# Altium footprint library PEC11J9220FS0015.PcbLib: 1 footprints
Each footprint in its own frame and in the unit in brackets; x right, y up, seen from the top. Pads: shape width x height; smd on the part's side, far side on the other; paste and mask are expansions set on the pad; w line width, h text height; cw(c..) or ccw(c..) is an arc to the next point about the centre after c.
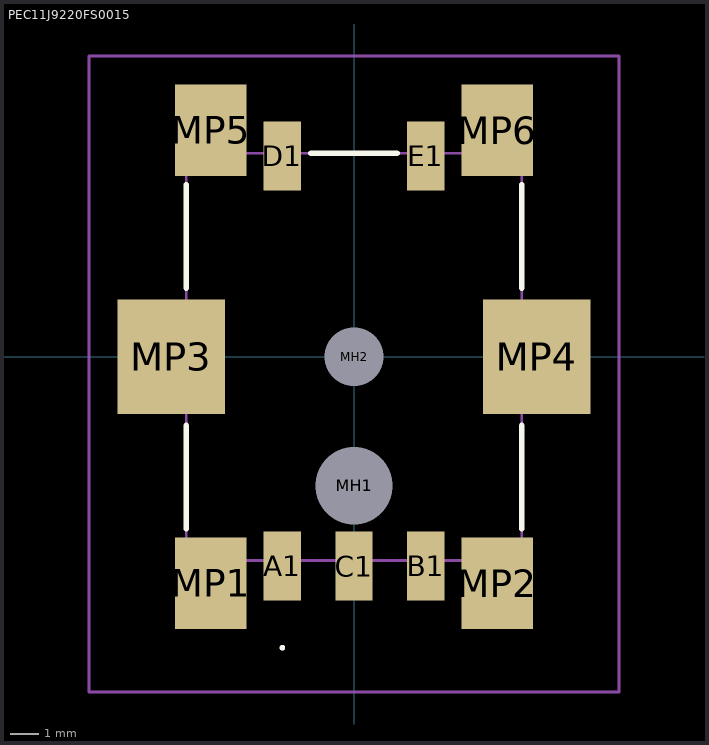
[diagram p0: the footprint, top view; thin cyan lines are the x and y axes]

## PEC11J9220FS0015 [mm]
pads (13):
  rect 1.3x2.4 smd: A1(-2.5,-7.3) B1(2.5,-7.3) C1(0,-7.3) D1(-2.5,7) E1(2.5,7)
  round 1.345 hole 2.69 unplated: MH1(0,-4.5)
  round 1.025 hole 2.05 unplated: MH2(0,0)
  rect 2.5x3.2 smd: MP1(-5,-7.9) MP2(5,-7.9) MP5(-5,7.9) MP6(5,7.9)
  rect 3.75x4 smd: MP3(-6.375,0) MP4(6.375,0)
Top Overlay:
  lines w0.1: -2.5,-10.2 -2.5,-10.2 ; -2.5,-10.2 ccw(c-2.5,-10.15) -2.5,-10.1 ; -2.5,-10.2 cw(c-2.5,-10.15) -2.5,-10.1 ; -2.5,-10.1 -2.5,-10.1
  lines w0.2: -5.85,-6 -5.85,-2.4 ; -5.85,2.4 -5.85,6 ; -1.5,7.1 1.5,7.1 ; 5.85,-6 5.85,-2.4 ; 5.85,2.4 5.85,6
Mechanical 15:
  lines w0.1: -5.85,-7.1 5.85,-7.1 5.85,7.1 -5.85,7.1 -5.85,-7.1
Mechanical 20:
  lines w0.1: -9.25,-11.7 9.25,-11.7 9.25,10.5 -9.25,10.5 -9.25,-11.7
